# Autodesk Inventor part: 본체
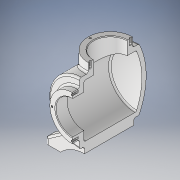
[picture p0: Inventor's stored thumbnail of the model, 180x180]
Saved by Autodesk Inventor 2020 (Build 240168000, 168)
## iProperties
Created: 2023-12
Part Number: 본체
Material: 일반
Document SubType Name: Modeling
Designer: 1강의실14
Density: 1 g/cm^3
Appearance: 기본값
Author: 1강의실14
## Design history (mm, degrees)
sketch "스케치2" dims "d7" = 226
  geometry: L1 (0, -99.2)-(0, 217.2) reference; L2 (0, 54)-(50, 54); L3 (50, 54)-(50, -54); L4 (50, -54)-(0, -54); 4 further points
  constraints: 6 end point, 2 point on line, 1 horizontal, 1 horizontal alignment, 1 midpoint, 1 perpendicular, 1 vertical alignment, 3 other
  dimensions: "d3" = 50 distance of L2.start L2.end; "d4" = 108 distance of L2.end L3.end; "d5" = 50 distance of L3.end L4.end
revolve "회전1" sketch "스케치2" stored, may be unused: angle "d6" = 90 deg
feature "쉘1" dims "d8" = 7
sketch "스케치5"
  geometry: C1 r 36 at (0, 0); 1 further point
  constraints: 1 centre point, 1 coincident
  dimensions: "d15" = 72 diameter of C1
extrude "돌출3" join sketch "스케치5" distance "d16" = 12; taper "d17" = 0 deg
node "작업 평면1"
sketch "스케치4"
  geometry: L1 (36, 66)-(-36, 66) reference; C1 r 36 at (0, 4); 1 further point
  constraints: 1 centre point, 1 vertical alignment
  dimensions: "d13" = 72 diameter of C1; "d18" = 62 distance from line of C1.centre L1
extrude "돌출4" join sketch "스케치4" stored distance "d19" = 12; taper "d20" = 0 deg
sketch "스케치6"
  geometry: C1 r 36 at (0, 0) reference; C2 r 27 at (0, 0); 1 further point
  constraints: 1 centre point, 1 coincident
  dimensions: "d21" = 54 diameter of C2
extrude "돌출5" cut sketch "스케치6" distance "d22" = 46; taper "d23" = 0 deg
sketch "스케치7"
  geometry: C1 r 27 at (0, 0); 1 further point
  constraints: 1 centre point, 1 coincident
  dimensions: "d24" = 54 diameter of C1
extrude "돌출6" cut sketch "스케치7" distance "d25" = 46; taper "d26" = 0 deg
sketch "스케치8"
  geometry: L1 (0, -73)-(0, 88) reference; L2 (26.694, -42.278)-(62, -67); L3 (62, -67)-(62, -77); L4 (62, -77)-(-62, -77); L5 (-62, -77)-(-62, -67); L6 (-62, -67)-(-26.694, -42.278); A1 r 50 centre (0, 0) between (26.694, -42.278) and (-26.694, -42.278) reference; 2 further points
  constraints: 10 end point, 2 perpendicular, 2 point on circle, 1 midpoint, 1 vertical, 1 vertical alignment
  dimensions: "d27" = 10 distance of L2.end L3.end; "d28" = 124 distance of L3.end L4.end; "d29" = 10 distance of L4.end L5.end; "d30" = 55 deg angle of L3 L2; "d31" = 55 deg angle of L6 L5; "d32" = 77 distance from line of L4 point (0, 0)
extrude "돌출7" join sketch "스케치8" distance "d33" = 46; taper "d34" = 0 deg; dims "d82" = 34, "d83" = 0
sketch "스케치9"
  geometry: L1 (62, -77)-(-62, -77) reference; A1 r 52.096 centre (0, -112.096) between (38.5, -77) and (-38.5, -77); 2 further points
  constraints: 3 point on circle, 2 point on line, 1 centre point, 1 vertical alignment
  dimensions: "d35" = 77 distance of A1.end A1.start; "d36" = 17 distance from line of L1 point (0, -60)
extrude "돌출8" cut sketch "스케치9" distance "d37" = 80; taper "d38" = 0 deg
sketch "스케치10"
  geometry: L1 (0, 0)-(0, 32.5)
  constraints: 2 end point, 1 vertical
  dimensions: "d39" = 32.5 distance of L1.start L1.end
hole "구멍1" sketch "스케치10" at (0, 32.5) diameter "d40" = 3.242; stored, may be unused: countersink angle "d44" = 90 deg, drill point angle "d46" = 118 deg; dims "d41" = 8, "d42" = 4, "d43" = 2, "d45" = 10
sketch "스케치11"
  geometry: L1 (0, 0)-(-32.5, 0); C1 r 36 at (0, 0) reference; 1 further point
  constraints: 2 end point, 1 horizontal
  dimensions: "d50" = 32.5 distance of L1.start L1.end
hole "구멍2" sketch "스케치11" at (-32.5, 0) diameter "d51" = 3.242; stored, may be unused: countersink angle "d55" = 90 deg, drill point angle "d57" = 118 deg; dims "d52" = 8, "d53" = 4, "d54" = 2, "d56" = 10
fillet "모깎기1" dims "d69" = 3
fillet "모깎기2" dims "d70" = 3
fillet "모깎기3" dims "d71" = 3
fillet "모깎기5" dims "d74" = 3
chamfer "모따기1" distance "d75" = 1; stored, may be unused: second distance "d76" = 2, angle "d77" = 45 deg
node "작업 평면2"
sketch "스케치15"
  geometry: L1 (36, 66)-(-36, 66) reference; 2 further points
  constraints: 1 vertical alignment, 1 other
  dimensions: "d79" = 62 distance from line of L1 point (0, 4)
feature "엠보싱1" sketch "스케치15" dims "d3" = 50, "d4" = 108, "d5" = 50, "d7" = 226, "d20" = 0, "d80" = 0.5, "d81" = 0
fillet "모깎기6" dims "d101" = 3
sketch "스케치16"
  geometry: L1 (0, 0)-(0, 80) reference; L2 (-23.5, 80)-(0, 80) reference; C1 r 4.5 at (-8, 60); 1 further point
  constraints: 1 centre point
  dimensions: "d84" = 9 diameter of C1; "d85" = 8 distance from line of L1 C1.centre; "d86" = 20 distance from line of L2 C1.centre
extrude "돌출11" cut sketch "스케치16" distance "d87" = 6; taper "d88" = 0 deg
sketch "스케치17"
  geometry: L1 (15, 0)-(0, 0); L2 (15, 7)-(0, 7); L3 (0, -7)-(15, -7); C1 r 4.5 at (0, 0) reference; A1 r 7 centre (15, 0) between (15, -7) and (15, 7); A2 r 7 centre (0, 0) between (0, 7) and (0, -7); 2 further points
  constraints: 8 end point, 4 point on circle, 4 tangent, 2 centre point, 1 horizontal, 1 midpoint, 1 parallel
  dimensions: "d89" = 14 diameter of A2; "d90" = 15 distance of L2.start L2.end
extrude "돌출12" cut sketch "스케치17" distance "d91" = 20.75; taper "d92" = 0 deg
sketch "스케치18"
  geometry: C1 r 4.5 at (-8, 60) reference; C2 r 4.5 at (-8, 20); 1 further point
  constraints: 1 centre point, 1 vertical alignment
  dimensions: "d93" = 9 diameter of C2; "d94" = 40 distance of C2.centre C1.centre
extrude "돌출13" cut sketch "스케치18" distance "d95" = 6; taper "d96" = 0 deg
sketch "스케치19"
  geometry: L1 (15, 0)-(0, 0); L2 (15, 7)-(0, 7); L3 (0, -7)-(15, -7); C1 r 4.5 at (0, 0) reference; A1 r 7 centre (15, 0) between (15, -7) and (15, 7); A2 r 7 centre (0, 0) between (0, 7) and (0, -7); 2 further points
  constraints: 8 end point, 4 point on circle, 4 tangent, 2 centre point, 1 horizontal, 1 midpoint, 1 parallel
  dimensions: "d97" = 14 diameter of A2; "d98" = 15 distance of L2.start L2.end
extrude "돌출14" cut sketch "스케치19" distance "d99" = 20; taper "d100" = 0 deg
feature "분할2"
node "솔리드2"
pattern_circular "원형 패턴1" dims angle "d48" = 360 deg
pattern_circular "원형 패턴2" dims angle "d59" = 360 deg
mirror "미러3"
mirror "미러4"
feature "A9D066F2-1C7D-4E18-AEED-F7BC21143FA4" dims "d40" = 3.242, "d41" = 8, "d42" = 4, "d43" = 2, "d44" = 90 deg, "d45" = 10, "d46" = 118 deg
other parameters: "d12" = 65, "d78" = 58.25
